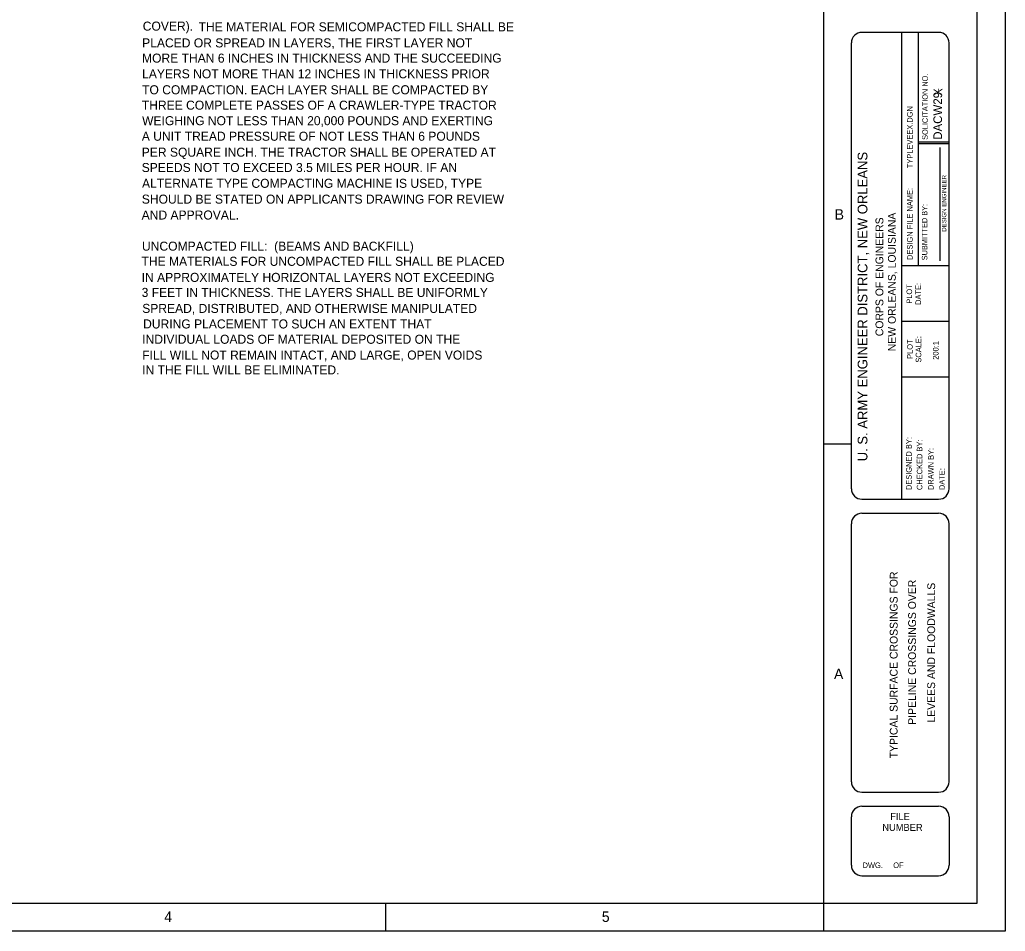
# Model space of a CAD drawing. Extents: x 2127959 to 2137375, y 2146193 to 2153470.
# Drawn here: x 2133592 to 2137375, y 2146193 to 2149692 of the extents above; entities that cross this region are included whole.
import ezdxf

# ---------------------------------------------------------------- set-up
doc = ezdxf.new("R2010")
doc.units = 0
for name, color, linetype in [('Level 1', 7, 'Continuous'), ('Level 2', 7, 'Continuous'), ('Level 7', 7, 'Continuous')]:
    doc.layers.add(name, color=color, linetype=linetype)

msp = doc.modelspace()

# ---------------------------------------------------------------- linework, layer by layer
at = {"layer": 'Level 1'}
for p, q in [((2137266.816, 2146300.478), (2137266.816, 2153362.032)), ((2137123.012, 2149643.798), (2136817.441, 2149643.798)), ((2136976.642, 2149643.798), (2136976.668, 2147851.445)), ((2137039.752, 2149643.798), (2137039.752, 2148747.618)), ((2137158.962, 2149221.914), (2137039.752, 2149221.893)), ((2137158.962, 2148747.627), (2136976.668, 2148747.627)), ((2137158.979, 2148533.642), (2136976.642, 2148533.642)), ((2137158.979, 2148319.653), (2136976.642, 2148319.653)), ((2136678.794, 2148064.574), (2136784.08, 2148064.574)), ((2136824.204, 2146726.743), (2137118.858, 2146726.743)), ((2136824.204, 2146672.814), (2137118.858, 2146672.814)), ((2136824.18, 2146405.747), (2137118.842, 2146405.747)), ((2128280.166, 2146300.478), (2136678.776, 2146300.478)), ((2134996.862, 2146192.626), (2134996.862, 2146300.478)), ((2136612.025, 2146300.478), (2136719.881, 2146300.478)), ((2136678.794, 2146192.626), (2136678.776, 2146300.478)), ((2136678.776, 2146300.478), (2137266.816, 2146300.478))]:
    msp.add_line(p, q, dxfattribs=at)
msp.add_lwpolyline([(2127959.193, 2153469.025), (2137374.681, 2153469.025), (2137374.681, 2146193.484), (2127959.193, 2146193.484)], close=True, dxfattribs=at)
for points in [[(2136678.776, 2146300.478), (2136678.794, 2153362.027)], [(2137118.858, 2149643.798), (2136824.204, 2149643.798)], [(2136784.08, 2147891.563), (2136784.08, 2149603.675)], [(2137158.962, 2147891.569), (2137158.962, 2149603.673)], [(2136824.18, 2147851.445), (2137118.858, 2147851.445)], [(2136824.18, 2147797.529), (2137118.858, 2147797.529)], [(2136784.056, 2146766.864), (2136784.08, 2147757.404)], [(2137158.962, 2146766.843), (2137158.979, 2147757.404)], [(2136784.08, 2146445.885), (2136784.08, 2146632.69)], [(2137158.962, 2146632.685), (2137158.962, 2146445.885)]]:
    msp.add_lwpolyline(points, dxfattribs=at)
for centre, start, end in [((2136824.17, 2149603.674), 90, 180), ((2137118.829, 2149603.674), 0, 90), ((2136824.17, 2147891.568), 180, 270), ((2137118.829, 2147891.568), 270, 0), ((2136824.17, 2147757.399), 90, 180), ((2137118.829, 2147757.399), 0, 90), ((2136824.17, 2146766.856), 180, 270), ((2137118.829, 2146766.856), 270, 0), ((2136824.17, 2146632.686), 90, 180), ((2137118.829, 2146632.686), 0, 90), ((2136824.17, 2146445.876), 180, 270), ((2137118.829, 2146445.876), 270, 0)]:
    msp.add_arc(centre, 40.122, start, end, dxfattribs=at)
at = {"layer": 'Level 2'}
for p, q in [((2137157.417, 2149215.716), (2137039.752, 2149215.716)), ((2137124.47, 2148766.784), (2137124.47, 2149202.12))]:
    msp.add_line(p, q, dxfattribs=at)

# ---------------------------------------------------------------- texts
at = {"layer": 'Level 1'}
for s, height, p in [('COVER).', 34.657, (2134064.198, 2149650.391)), ('THE MATERIAL FOR SEMICOMPACTED FILL SHALL BE', 34.657, (2134278.661, 2149647.615)), ('PLACED OR SPREAD IN LAYERS, THE FIRST LAYER NOT', 34.657, (2134061.882, 2149586.006)), ('MORE THAN 6 INCHES IN THICKNESS AND THE SUCCEEDING', 34.657, (2134061.458, 2149527.551)), ('LAYERS NOT MORE THAN 12 INCHES IN THICKNESS PRIOR', 34.657, (2134061.882, 2149467.297)), ('TO COMPACTION. EACH LAYER SHALL BE COMPACTED BY', 34.657, (2134061.697, 2149406.023)), ('THREE COMPLETE PASSES OF A CRAWLER-TYPE TRACTOR', 34.657, (2134060.606, 2149346.87)), ('WEIGHING NOT LESS THAN 20,000 POUNDS AND EXERTING', 34.657, (2134061.694, 2149287.313)), ('A UNIT TREAD PRESSURE OF NOT LESS THAN 6 POUNDS', 34.657, (2134060.606, 2149227.651)), ('PER SQUARE INCH. THE TRACTOR SHALL BE OPERATED AT', 34.657, (2134060.395, 2149166.427)), ('SPEEDS NOT TO EXCEED 3.5 MILES PER HOUR. IF AN', 34.657, (2134060.182, 2149107.56)), ('ALTERNATE TYPE COMPACTING MACHINE IS USED, TYPE', 34.657, (2134061.509, 2149046.879)), ('SHOULD BE STATED ON APPLICANTS DRAWING FOR REVIEW', 34.657, (2134060.633, 2148986.142)), ('AND APPROVAL.', 34.657, (2134059.996, 2148925.159)), ('B', 40.073, (2136719.881, 2148924.806)), ('UNCOMPACTED FILL:  (BEAMS AND BACKFILL)', 34.657, (2134061.323, 2148805.594)), ('THE MATERIALS FOR UNCOMPACTED FILL SHALL BE PLACED', 34.657, (2134059.423, 2148747.414)), ('IN APPROXIMATELY HORIZONTAL LAYERS NOT EXCEEDING ', 34.657, (2134060.042, 2148685.725)), ('3 FEET IN THICKNESS. THE LAYERS SHALL BE UNIFORMLY', 34.657, (2134060.041, 2148628.047)), ('SPREAD, DISTRIBUTED, AND OTHERWISE MANIPULATED', 34.657, (2134062.152, 2148566.653)), ('DURING PLACEMENT TO SUCH AN EXTENT THAT ', 34.657, (2134065.602, 2148507.022)), ('INDIVIDUAL LOADS OF MATERIAL DEPOSITED ON THE', 34.657, (2134062.152, 2148448.171)), ('FILL WILL NOT REMAIN INTACT, AND LARGE, OPEN VOIDS ', 34.657, (2134062.152, 2148387.522)), ('IN THE FILL WILL BE ELIMINATED.', 34.657, (2134062.152, 2148330.368)), ('A', 40.073, (2136717.31, 2147160.704)), ('FILE', 26.7002, (2136933.088, 2146619.983)), ('NUMBER', 26.7002, (2136902.692, 2146578.12)), ('DWG.     OF  ', 21.398, (2136826.894, 2146435.387)), ('4', 40.073, (2134146.888, 2146228.569)), ('5', 40.073, (2135826.252, 2146228.569))]:
    msp.add_text(s, height=height, dxfattribs=at).set_placement(p)
for s, height, rotation, p in [('SOLICITATION NO.', 21.12151, 90, (2137077.214, 2149231.108)), ('X', 32.947, 90, (2137132.627, 2149399.196)), ('TYPLEVEEX.DGN', 21.397, 90, (2137019.05, 2149122.05)), ('U. S. ARMY ENGINEER DISTRICT, NEW ORLEANS', 37.4461, 90, (2136845.528, 2147996.851)), ('DESIGN ENGINEER', 16.89413, 90, (2137148.256, 2148878.245)), ('DESIGN FILE NAME:', 21.39885, 90, (2137019.05, 2148769.973)), ('SUBMITTED BY:', 21.12151, 90, (2137075.603, 2148768.58)), ('NEW ORLEANS, LOUISIANA', 29.95673, 90, (2136954.334, 2148419.442)), ('CORPS OF ENGINEERS', 29.95673, 90, (2136906.6, 2148477.174)), ('PLOT', 21.3989, 90, (2137017.06, 2148601.94)), ('DATE:', 21.3989, 90, (2137051.2, 2148597.457)), ('PLOT', 21.3975, 90, (2137019.16, 2148390.191)), ('SCALE:', 21.3975, 90, (2137052.217, 2148375.74)), ('200:1', 21.3971, 90, (2137118.502, 2148386.886)), ('DESIGNED BY:', 21.39885, 90, (2137015.386, 2147886.486)), ('CHECKED BY:', 21.39885, 90, (2137056.48, 2147886.482)), ('DRAWN BY:', 21.3989, 90, (2137099.674, 2147886.486)), ('DATE:', 21.3989, 90, (2137142.436, 2147886.486)), ('TYPICAL SURFACE CROSSINGS FOR', 29.97896, 89.998783, (2136961.406, 2146856.721)), ('PIPELINE CROSSINGS OVER', 29.97896, 89.998783, (2137031.976, 2146985.46)), ('LEVEES AND FLOODWALLS', 29.97896, 89.998783, (2137105.341, 2146993.762))]:
    msp.add_text(s, height=height, rotation=rotation, dxfattribs=at).set_placement(p)
at = {"layer": 'Level 7'}
msp.add_text('DACW29-', height=32.947, rotation=90, dxfattribs=at).set_placement((2137131.73, 2149231.372))

doc.saveas('drawing.dxf')
